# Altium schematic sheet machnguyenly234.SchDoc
size A; SheetNumber: 1; SheetTotal: 1
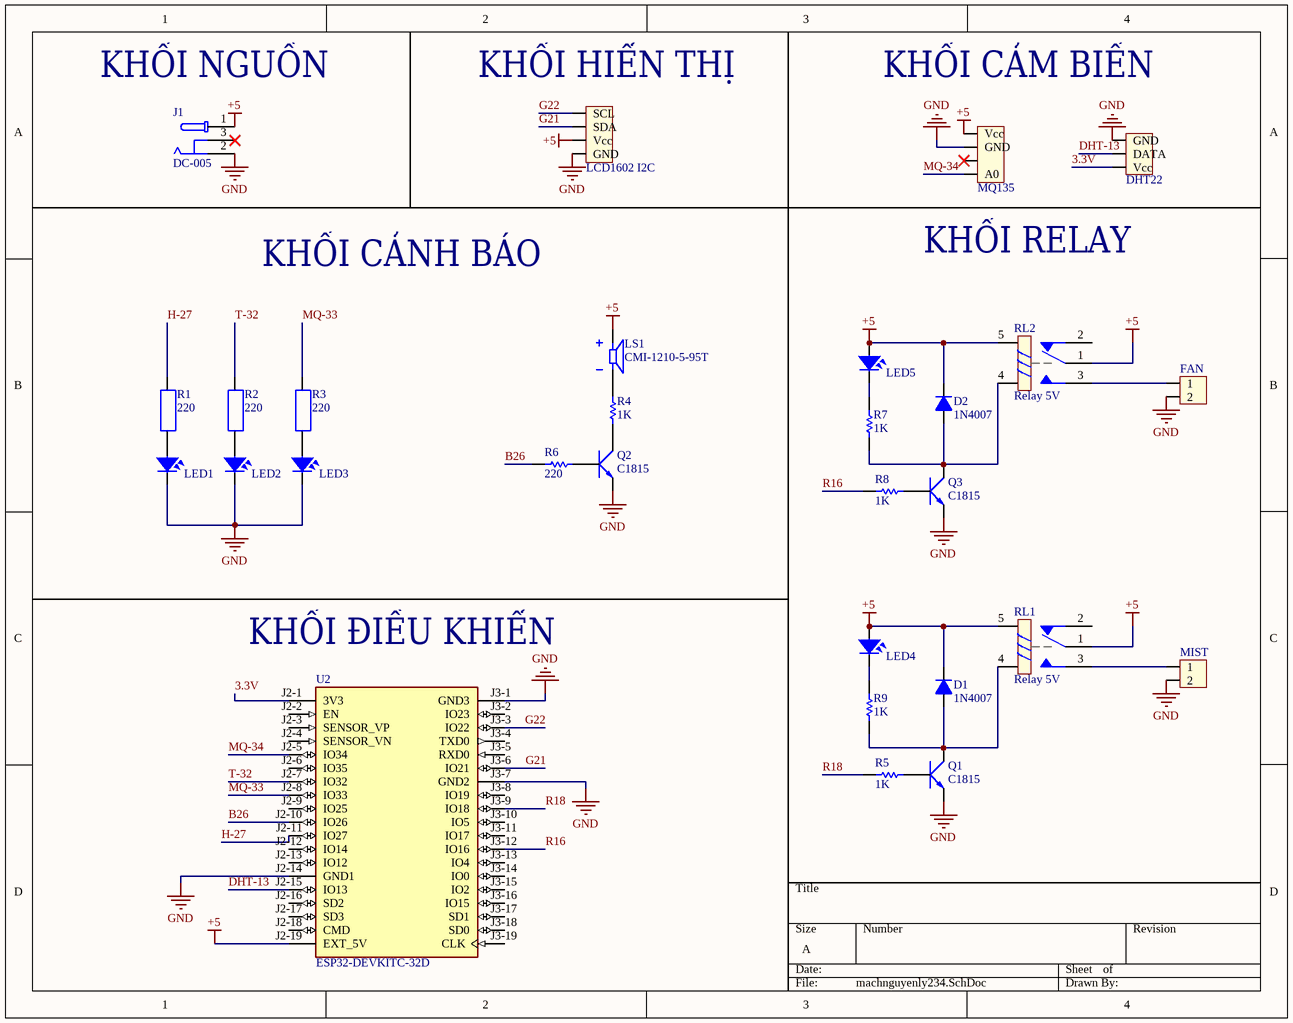
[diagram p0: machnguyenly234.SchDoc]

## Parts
D1  1N4007  [D1A]
D2  1N4007  [D1A]
DHT22  DHT22  [HED3]
FAN  Header 2  [HED2]  (value not drawn)
J1  DC-005  [MPD_EJ503B]
LCD  LCD1602 I2C  [HED4]
LED1  LED  [LED-3]  (value not drawn)
LED2  LED  [LED-3]  (value not drawn)
LED3  LED  [LED-3]  (value not drawn)
LED4  LED  [LED-3]  (value not drawn)
LED5  LED  [LED-3]  (value not drawn)
LS1  CMI-1210-5-95T  [XDCR_CMI-1210-5-95T]
MIST  Header 2  [HED2]  (value not drawn)
MQ135  MQ135  [HED4]
Q1  C1815  [QTO-92]
Q2  C1815  [QTO-92]
Q3  C1815  [QTO-92]
R1  220  [R1W]
R2  220  [R1W]
R3  220  [R1W]
R4  value 1K  [R1/4W]  (hidden comment: Res1)
R5  value 1K  [R1/4W]  (hidden comment: Res1)
R6  value 220  [R1/4W]  (hidden comment: Res1)
R7  value 1K  [R1/4W]  (hidden comment: Res1)
R8  value 1K  [R1/4W]  (hidden comment: Res1)
R9  value 1K  [R1/4W]  (hidden comment: Res1)
RL1  Relay 5V  [RL_SPDT_10A]
RL2  Relay 5V  [RL_SPDT_10A]
U2  ESP32-DEVKITC-32D  [MODULE_ESP32-DEVKITC-32D]

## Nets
+5: D1.2(K) D2.2(K) J1.1 LCD.3(Vcc) LED4.1 LED5.1 LS1.P MQ135.1(Vcc) RL1.1 RL1.5 RL2.1 RL2.5 U2.J2-19(EXT_5V)
GND: DHT22.1(GND) FAN.2 J1.2 LCD.4(GND) LED1.2 LED2.2 LED3.2 MIST.2 MQ135.2(GND) Q1.1(E) Q2.1(E) Q3.1(E) U2.J2-14(GND1) U2.J3-1(GND3) U2.J3-7(GND2)
3.3V: DHT22.3(Vcc) U2.J2-1(3V3)
B26: R6.2 U2.J2-10(IO26)
DHT-13: DHT22.2(DATA) U2.J2-15(IO13)
G21: LCD.2(SDA) U2.J3-6(IO21)
G22: LCD.1(SCL) U2.J3-3(IO22)
H-27: R1.1 U2.J2-11(IO27)
MQ-33: R3.1 U2.J2-8(IO33)
MQ-34: MQ135.4(A0) U2.J2-5(IO34)
R16: R8.2 U2.J3-12(IO16)
R18: R5.2 U2.J3-9(IO18)
T-32: R2.1 U2.J2-7(IO32)
NetD1_1: D1.1(A) Q1.2(C) R9.2 RL1.4
NetD2_1: D2.1(A) Q3.2(C) R7.2 RL2.4
NetFAN_1: FAN.1 RL2.3
NetLED1_1: LED1.1 R1.2
NetLED2_1: LED2.1 R2.2
NetLED3_1: LED3.1 R3.2
NetLED4_2: LED4.2 R9.1
NetLED5_2: LED5.2 R7.1
NetLS1_N: LS1.N R4.1
NetMIST_1: MIST.1 RL1.3
NetQ1_3: Q1.3(B) R5.1
NetQ2_2: Q2.2(C) R4.2
NetQ2_3: Q2.3(B) R6.1
NetQ3_3: Q3.3(B) R8.1

Not connected (* = marked no-connect by the designer): J1 3*; MQ135 3*; RL1 2; RL2 2; U2 J2-2(EN) J2-3(SENSOR_VP) J2-4(SENSOR_VN) J2-6(IO35) J2-9(IO25) J2-12(IO14) J2-13(IO12) J2-16(SD2) J2-17(SD3) J2-18(CMD) J3-2(IO23) J3-4(TXD0) J3-5(RXD0) J3-8(IO19) J3-10(IO5) J3-11(IO17) J3-13(IO4) J3-14(IO0) J3-15(IO2) J3-16(IO15) J3-17(SD1) J3-18(SD0) J3-19(CLK)

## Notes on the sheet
- (near J1) KHỐI NGUỒN
- (near LCD) KHỐI HIỂN THỊ
- KHỐI CẢM BIẾN
- KHỐI CẢNH BÁO
- KHỐI RELAY
- (near U2) KHỐI ĐIỀU KHIỂN

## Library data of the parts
D1 D2 = D1A: Diode 1A
DHT22 = Hed3: Header 3 (Green)
FAN MIST = Hed2: Header 2 (Green)
J1 = EJ503B: CONN PWR JACK 2.5X5.5MM SOLDER; MF: MPD (Memory Protection Devices)
LCD MQ135 = Hed4: Header 4 (Green)
LED1-LED5 = LED: LED Single colour Green and Red; Value: LED 3 ly Single Colour
LS1 = CMI-1210-5-95T: 12 mm, 5 Vdc, 98 dB, Through Hole, Magnetic Audio Indicator Buzzer; MF: Same Sky
Q1-Q3 = C1815: NPN 600mW, ECB
R1-R3 = R1W: Resistor 1W; Value: R1W - 100
R4-R9 = Res1_4: Resistor; Manufacturer: Generic Components; Class: Passive
RL1 RL2 = Relay 1: Relay SPDT,10A - 12VDC 5 Pin; Value: Relay SPDT, 10A, 12V
U2 = ESP32-DEVKITC-32D: WiFi Development Tools (802.11) ESP32 General Development Kit, ESP32-WROOM-32D on the board; MF: Espressif Systems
